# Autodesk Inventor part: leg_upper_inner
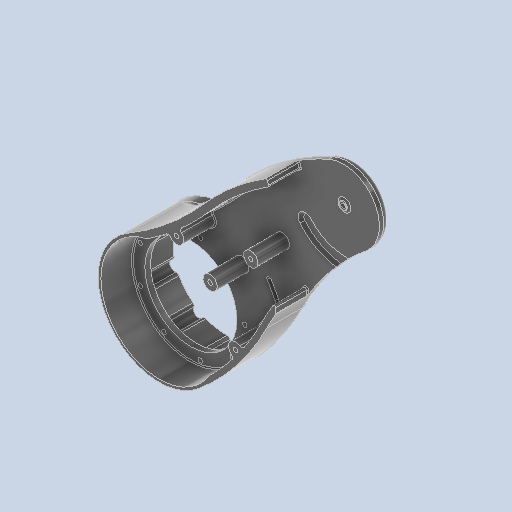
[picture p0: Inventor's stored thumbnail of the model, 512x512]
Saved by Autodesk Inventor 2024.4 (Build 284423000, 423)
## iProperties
Created: 2026-01
Part Number: leg_upper_inner
Material: Generic
Document SubType Name: Modeling
Designer: AdminForWorker
Density: 1 g/cm^3
Appearance: Default
Title: leg_upper_inner
Author: AdminForWorker
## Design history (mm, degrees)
feature "Body1"
body "Solid1"
